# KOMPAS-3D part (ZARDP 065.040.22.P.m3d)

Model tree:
1. Булева операция:1
2. Булева операция:2
3. Булева операция:3
4. Булева операция:4
5. Булева операция:5
6. Булева операция:6
7. Булева операция:7
8. Булева операция:8
9. Булева операция:9
10. Булева операция:10
